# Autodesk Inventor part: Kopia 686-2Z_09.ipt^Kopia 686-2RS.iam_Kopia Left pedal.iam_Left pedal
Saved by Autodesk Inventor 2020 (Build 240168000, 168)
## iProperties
Created: 2017-10
Part Number: Kopia 686-2Z_09.ipt^Kopia 686-2RS.iam_Kopia Left pedal.iam_Left pedal
Material: Ogólny
Document SubType Name: Modeling
Designer: Tomasz
Density: 1 g/cm^3
Appearance: Domyślna
Sending System: SolidWorks 2017
Last Author: Tomasz
Last Saved: 2017-10-01
Author: Tomasz
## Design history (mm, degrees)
